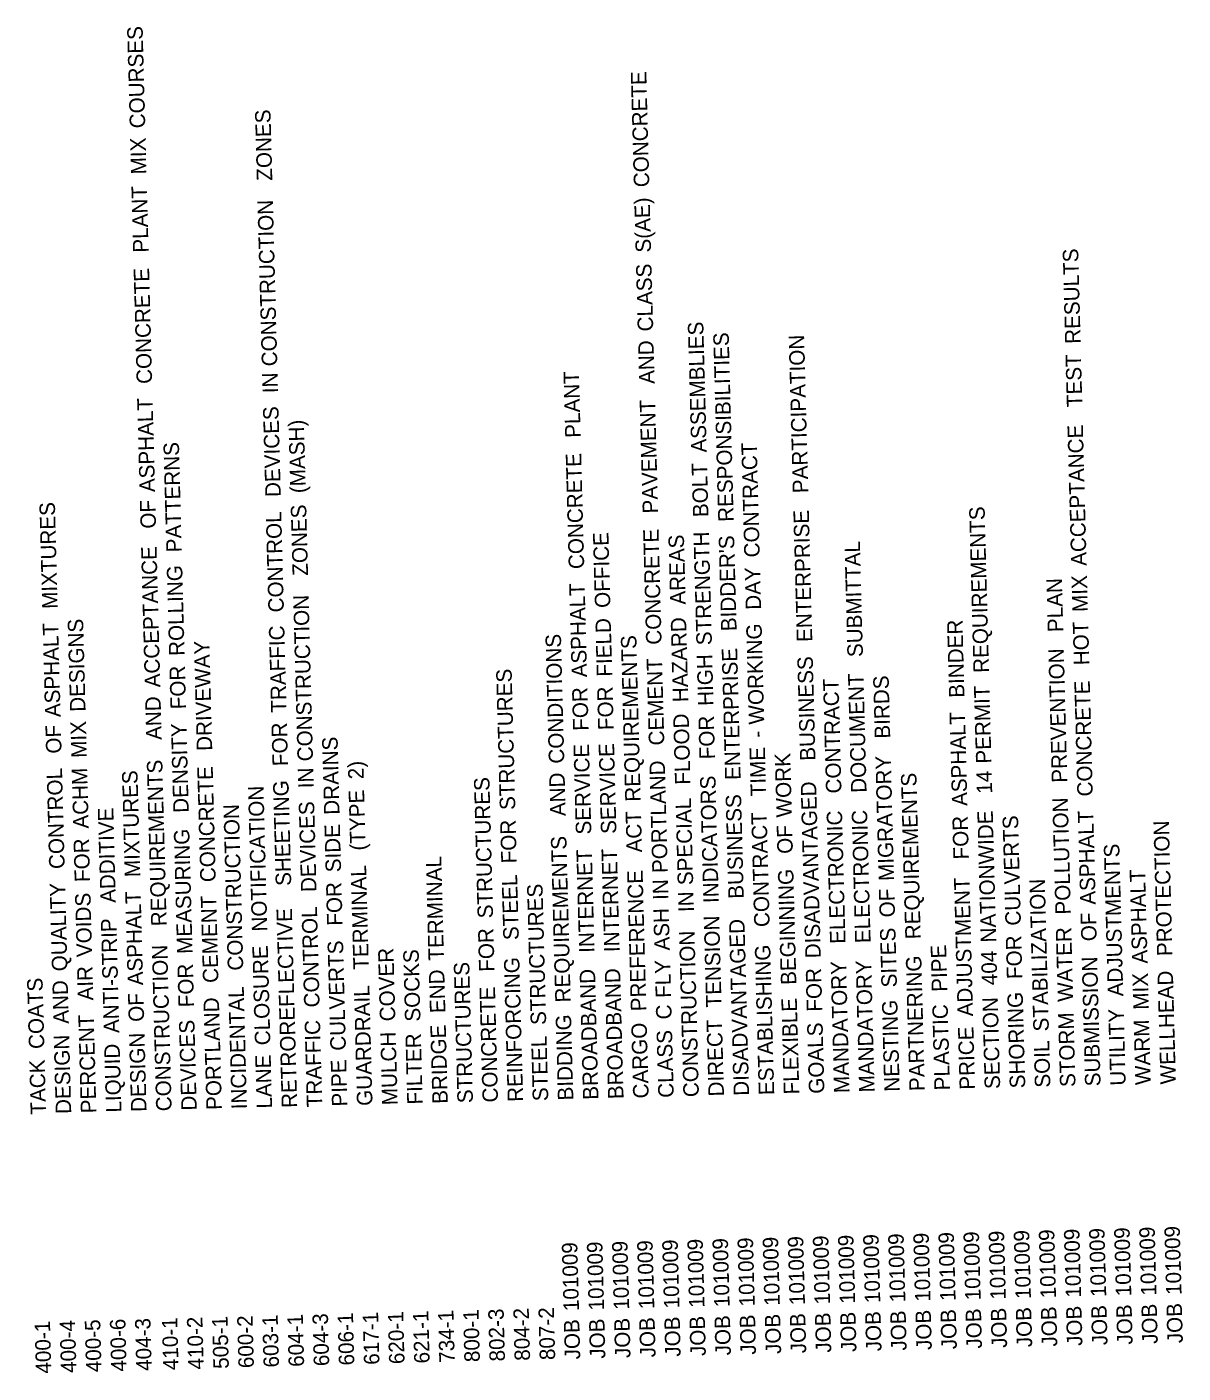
# Model space of a CAD drawing. Extents: x 1930579 to 1931706, y 595585 to 597808.
# Drawn here: x 1931149 to 1931579, y 595592 to 596094 of the extents above; entities that cross this region are included whole.
import ezdxf

# ---------------------------------------------------------------- set-up
doc = ezdxf.new("R2010")
doc.units = 0
doc.layers.add('Default', color=7, linetype='Continuous')

msp = doc.modelspace()

# ---------------------------------------------------------------- texts
at = {"layer": 'Default'}
for s, p in [(' COURSES', (1931192.77, 596054.16)), (' CONCRETE', (1931380.63, 596032.21)), (' ZONES', (1931240.11, 596034.63)), (' MIX', (1931193.23, 596036.99)), (' PLANT', (1931194.01, 596007.82)), (' CONSTRUCTION', (1931241.97, 595965.47)), (' S(AE)', (1931381.28, 596007.84)), (' RESULTS', (1931541.37, 595973.84)), (' CONCRETE', (1931195.33, 595958.91)), (' CLASS', (1931382.07, 595978.46)), (' ASSEMBLIES', (1931402.01, 595933.32)), (' AND', (1931382.6, 595958.89)), (' RESPONSIBILITIES', (1931412.07, 595907.51)), (' PARTICIPATION', (1931439.87, 595918.19)), (' TEST', (1931542, 595950.26)), (' IN', (1931242.24, 595955.45)), (' PLANT', (1931355.04, 595938.82)), (' ASPHALT', (1931196.41, 595918.56)), (' DEVICES', (1931243.28, 595916.77)), (' PAVEMENT', (1931383.89, 595910.62)), (' (MASH)', (1931252.6, 595918.18)), (' ACCEPTANCE', (1931543.59, 595891.09)), (' PATTERNS', (1931206.38, 595896.15)), (' CONTRACT', (1931421.78, 595894.25)), (' CONCRETE', (1931356.36, 595889.91)), (' BOLT', (1931402.65, 595909.27)), (' MIXTURES', (1931160.12, 595875.08)), (' OF', (1931196.78, 595904.97)), (' ZONES', (1931253.43, 595887.42)), (' CONTROL', (1931244.43, 595873.76)), (' ENTERPRISE', (1931441.36, 595862.75)), (' REQUIREMENTS', (1931507.21, 595851.23)), (' CONCRETE', (1931385.2, 595861.71)), (' OFFICE', (1931366.11, 595875.44)), (' AREAS', (1931394.17, 595876.64)), (' STRENGTH', (1931403.94, 595861.52)), (" BIDDER'S", (1931413.16, 595866.76)), (' SUBMITTAL', (1931460.23, 595857.11)), (' ACCEPTANCE', (1931198.36, 595845.81)), (' ROLLING', (1931207.41, 595857.56)), (' DAY', (1931422.31, 595874.75)), (' ASPHALT', (1931357.44, 595849.56)), (' PLAN', (1931534.89, 595866.42)), (' MIX', (1931544.05, 595873.92)), (' CONSTRUCTION', (1931255.28, 595818.26)), (' ASPHALT', (1931161.21, 595834.72)), (' DESIGNS', (1931170.52, 595836.73)), (' TRAFFIC', (1931245.43, 595836.39)), (' FIELD', (1931366.8, 595849.81)), (' HAZARD', (1931395.14, 595840.3)), (' WORKING', (1931423.46, 595831.98)), (' BINDER', (1931498.09, 595841.96)), (' HOT', (1931544.59, 595854.07)), (' CONDITIONS', (1931348.94, 595817.4)), (' REQUIREMENTS', (1931377.41, 595803.22)), (' DRIVEWAY', (1931217.73, 595822.15)), (' ENTERPRISE', (1931414.65, 595811.32)), (' PREVENTION', (1931536.4, 595810.29)), (' FOR', (1931207.95, 595837.66)), (' CEMENT', (1931386.21, 595824.17)), (' HIGH', (1931404.54, 595838.92)), (' BUSINESS', (1931442.55, 595818.47)), (' STRUCTURES', (1931330.68, 595800.14)), (' CONTRACT', (1931452.24, 595806.28)), (' DOCUMENT', (1931461.59, 595806.53)), (' BIRDS', (1931470.41, 595826.72)), (' FOR', (1931357.97, 595829.65)), (' FOR', (1931367.33, 595829.9)), (' PERMIT', (1931508.12, 595817.41)), (' CONCRETE', (1931545.9, 595805.16)), (' AND', (1931198.89, 595826.23)), (' FLOOD', (1931395.97, 595809.55)), (' FOR', (1931405.08, 595819.02)), (' ASPHALT', (1931499.18, 595801.61)), (' OF', (1931161.57, 595821.14)), (' MIX', (1931170.98, 595819.56)), (' DENSITY', (1931208.98, 595799.07)), (' FOR', (1931245.97, 595816.48)), (' -', (1931423.59, 595827.13)), (' DRAINS', (1931265.18, 595798.35)), (' SERVICE', (1931359.01, 595790.98)), (' SERVICE', (1931368.37, 595791.23)), (' TIME', (1931424.17, 595805.23)), (' REQUIREMENTS', (1931200.75, 595756.82)), (' WORK', (1931433.75, 595797.37)), (' MIGRATORY', (1931471.84, 595773.7)), (' CONTROL', (1931162.73, 595778.14)), (' ACHM', (1931171.69, 595793.18)), (' MIXTURES', (1931190.9, 595775.13)), (' CONCRETE', (1931219.04, 595773.24)), (' IN', (1931255.55, 595808.24)), (' 2)', (1931274.19, 595811.57)), (' AND', (1931349.47, 595797.82)), (' PORTLAND', (1931387.49, 595776.65)), (' REQUIREMENTS', (1931481.78, 595751.96)), (' 14', (1931508.42, 595806.17)), (' NOTIFICATION', (1931238.26, 595754.84)), (' SHEETING', (1931247.17, 595771.84)), (' STRUCTURES', (1931322.4, 595759.75)), (' INDICATORS', (1931406.52, 595765.45)), (' DISADVANTAGED', (1931444.52, 595744.87)), (' (TYPE', (1931274.9, 595785.01)), (' SPECIAL', (1931396.97, 595772.12)), (' BUSINESS', (1931415.84, 595767.05)), (' POLLUTION', (1931537.72, 595761.15)), (' ADDITIVE', (1931181.79, 595765.51)), (' CONSTRUCTION', (1931229.29, 595740.28)), (' DEVICES', (1931256.59, 595769.56)), (' ACT', (1931377.92, 595784.29)), (' CONTRACT', (1931425.48, 595756.51)), (' ELECTRONIC', (1931453.74, 595750.27)), (' ELECTRONIC', (1931463.1, 595750.52)), (' NATIONWIDE', (1931509.91, 595750.75)), (' ASPHALT', (1931546.98, 595764.81)), (' SIDE', (1931265.76, 595776.91)), (' FOR', (1931331.21, 595780.24)), (' OF', (1931434.11, 595783.79)), (' FOR', (1931499.71, 595781.7)), (' CULVERTS', (1931519.1, 595757.03)), (' PROTECTION', (1931575.59, 595745.7)), (' FOR', (1931172.22, 595773.28)), (' MEASURING', (1931210.39, 595746.51)), (' REQUIREMENTS', (1931351.33, 595728.41)), (' INTERNET', (1931360.2, 595746.91)), (' INTERNET', (1931369.55, 595747.16)), (' ADJUSTMENTS', (1931557.26, 595730.67)), (' TERMINAL', (1931276.09, 595740.61)), (' TERMINAL', (1931304.09, 595744.02)), (' STEEL', (1931331.98, 595751.65)), (' PREFERENCE', (1931379.51, 595725.13)), (' IN', (1931387.76, 595766.63)), (' BEGINNING', (1931435.42, 595734.96)), (' ADJUSTMENT', (1931501.28, 595723.2)), (' STABILIZATION', (1931529.52, 595717.59)), (' ASPHALT', (1931566.3, 595742.87)), (' QUALITY', (1931163.75, 595740.02)), (' VOIDS', (1931172.97, 595745.31)), (' ASPHALT', (1931191.98, 595734.78)), (' FOR', (1931266.29, 595757.01)), (' STRUCTURES', (1931342.19, 595720.02)), (' IN', (1931397.24, 595762.1)), (' OF', (1931472.2, 595760.12)), (' CEMENT', (1931220.05, 595735.69)), ('RETROREFLECTIVE', (1931249.33, 595691.25)), (' CONTROL', (1931257.75, 595726.55)), (' ANTI-STRIP', (1931183.1, 595716.98)), (' ASH', (1931388.26, 595747.74)), (' TENSION', (1931407.56, 595726.55)), ('DISADVANTAGED', (1931417.75, 595695.77)), (' OF', (1931547.35, 595751.23)), (' FOR', (1931322.93, 595739.85)), ('CONSTRUCTION', (1931399.04, 595695.27)), (' SITES', (1931472.9, 595734.01)), (' FOR', (1931519.64, 595737.13)), (' WATER', (1931538.59, 595728.67)), ('CONSTRUCTION', (1931202.55, 595690)), (' CLOSURE', (1931239.4, 595712.45)), (' CULVERTS', (1931267.54, 595710.41)), (' COVER', (1931285.97, 595721.38)), ('ESTABLISHING', (1931427.11, 595696.03)), (' PIPE', (1931491.67, 595732.38)), (' SOCKS', (1931295.34, 595721.26)), ('STRUCTURES', (1931314.83, 595693.01)), ('REINFORCING', (1931333.54, 595693.51)), (' FLY', (1931388.74, 595730.11)), ('MANDATORY', (1931455.18, 595696.78)), ('MANDATORY', (1931464.53, 595697.03)), ('PARTNERING', (1931483.25, 595697.53)), (' 404', (1931510.33, 595734.85)), ('SUBMISSION', (1931548.74, 595699.29)), (' AIR', (1931173.41, 595729.13)), (' FOR', (1931210.93, 595726.61)), (' END', (1931304.62, 595724.45)), ('BROADBAND', (1931361.61, 595694.27)), ('BROADBAND', (1931370.97, 595694.52)), (' FOR', (1931445.06, 595724.97)), (' MIX', (1931566.76, 595725.7)), ('WELLHEAD', (1931576.81, 595700.04)), (' COATS', (1931155.16, 595711.08)), (' AND', (1931164.28, 595720.44)), ('INCIDENTAL', (1931230.62, 595690.75)), ('GUARDRAIL', (1931277.4, 595692.01)), ('CONCRETE', (1931324.18, 595693.26)), (' OF', (1931192.35, 595721.19)), ('PORTLAND', (1931221.26, 595690.5)), ('FLEXIBLE', (1931436.46, 595696.28)), ('NESTING', (1931473.89, 595697.28)), ('SECTION', (1931511.32, 595698.29)), ('SHORING', (1931520.67, 595698.54)), ('PERCENT', (1931174.48, 595689.24)), ('BIDDING', (1931352.25, 595694.02)), (' C', (1931388.95, 595722.07)), ('PLASTIC', (1931492.6, 595697.78)), ('STORM', (1931539.39, 595699.04)), ('UTILITY', (1931558.1, 595699.54)), ('DEVICES', (1931211.9, 595690.25)), ('TRAFFIC', (1931258.69, 595691.5)), ('BRIDGE', (1931305.47, 595692.76)), ('CARGO', (1931380.32, 595694.77)), ('DIRECT', (1931408.39, 595695.52)), ('GOALS', (1931445.82, 595696.53)), ('PRICE', (1931501.96, 595698.04)), ('WARM', (1931567.45, 595699.79)), ('DESIGN', (1931165.12, 595688.99)), ('DESIGN', (1931193.19, 595689.75)), ('MULCH', (1931286.76, 595692.26)), ('FILTER', (1931296.11, 595692.51)), ('STEEL', (1931342.9, 595693.77)), ('CLASS', (1931389.68, 595695.02)), ('SOIL', (1931530.03, 595698.79)), ('LIQUID', (1931183.83, 595689.5)), ('LANE', (1931239.97, 595691)), ('TACK', (1931155.76, 595688.74)), ('PIPE', (1931268.04, 595691.76)), (' 101009', (1931504.12, 595617.4)), (' 101009', (1931513.48, 595617.65)), (' 101009', (1931522.84, 595617.9)), (' 101009', (1931532.19, 595618.15)), (' 101009', (1931541.55, 595618.4)), (' 101009', (1931550.91, 595618.65)), (' 101009', (1931560.26, 595618.91)), (' 101009', (1931569.62, 595619.16)), (' 101009', (1931578.98, 595619.41)), (' 101009', (1931354.42, 595613.38)), (' 101009', (1931363.77, 595613.63)), (' 101009', (1931373.13, 595613.88)), (' 101009', (1931382.49, 595614.13)), (' 101009', (1931391.84, 595614.39)), (' 101009', (1931401.2, 595614.64)), (' 101009', (1931410.56, 595614.89)), (' 101009', (1931419.91, 595615.14)), (' 101009', (1931429.27, 595615.39)), (' 101009', (1931438.63, 595615.64)), (' 101009', (1931447.98, 595615.89)), (' 101009', (1931457.34, 595616.14)), (' 101009', (1931466.7, 595616.39)), (' 101009', (1931476.05, 595616.65)), (' 101009', (1931485.41, 595616.9)), (' 101009', (1931494.77, 595617.15)), ('617-1', (1931279.99, 595595.52)), ('620-1', (1931289.35, 595595.77)), ('621-1', (1931298.7, 595596.02)), ('734-1', (1931308.06, 595596.27)), ('800-1', (1931317.42, 595596.52)), ('802-3', (1931326.77, 595596.77)), ('804-2', (1931336.13, 595597.02)), ('807-2', (1931345.49, 595597.28)), ('JOB', (1931457.77, 595600.29)), ('JOB', (1931467.12, 595600.54)), ('JOB', (1931476.48, 595600.79)), ('JOB', (1931485.84, 595601.04)), ('JOB', (1931495.19, 595601.29)), ('JOB', (1931504.55, 595601.55)), ('JOB', (1931513.91, 595601.8)), ('JOB', (1931523.26, 595602.05)), ('JOB', (1931532.62, 595602.3)), ('JOB', (1931541.98, 595602.55)), ('JOB', (1931551.33, 595602.8)), ('JOB', (1931560.69, 595603.05)), ('JOB', (1931570.05, 595603.3)), ('JOB', (1931579.4, 595603.55)), ('400-1', (1931157.71, 595592.23)), ('400-4', (1931167.06, 595592.49)), ('400-5', (1931176.42, 595592.74)), ('400-6', (1931185.78, 595592.99)), ('404-3', (1931195.13, 595593.24)), ('410-1', (1931205.14, 595593.51)), ('410-2', (1931214.49, 595593.76)), ('505-1', (1931223.85, 595594.01)), ('600-2', (1931233.21, 595594.26)), ('603-1', (1931242.56, 595594.51)), ('604-1', (1931251.92, 595594.76)), ('604-3', (1931261.28, 595595.01)), ('606-1', (1931270.63, 595595.27)), ('JOB', (1931354.84, 595597.53)), ('JOB', (1931364.2, 595597.78)), ('JOB', (1931373.56, 595598.03)), ('JOB', (1931382.91, 595598.28)), ('JOB', (1931392.27, 595598.53)), ('JOB', (1931401.63, 595598.78)), ('JOB', (1931410.98, 595599.03)), ('JOB', (1931420.34, 595599.28)), ('JOB', (1931429.7, 595599.54)), ('JOB', (1931439.05, 595599.79)), ('JOB', (1931448.41, 595600.04))]:
    msp.add_text(s, height=5.76, rotation=91.5377, dxfattribs=at).set_placement(p)

doc.saveas('drawing.dxf')
